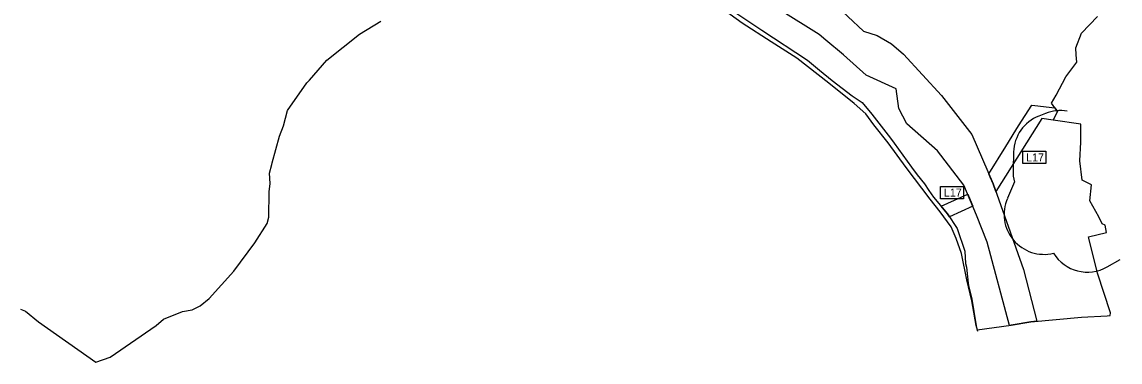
# Model space of a CAD drawing. Extents: x -547623 to -532764, y -1096714 to -1086523.
# Drawn here: x -540221 to -538849, y -1093364 to -1092939 of the extents above; entities that cross this region are included whole.
import ezdxf

# ---------------------------------------------------------------- set-up
doc = ezdxf.new("R2010")
doc.units = 0
for name, color, linetype in [('Vrstva 22', 7, 'Continuous'), ('Vrstva 23', 7, 'Continuous'), ('Vrstva 33', 7, 'Continuous'), ('Vrstva 36', 7, 'Continuous'), ('Vrstva 7', 7, 'Continuous')]:
    doc.layers.add(name, color=color, linetype=linetype)

msp = doc.modelspace()

# ---------------------------------------------------------------- linework, layer by layer
at = {"layer": 'Vrstva 22'}
for points in [[(-539330.4, -1092926.8), (-539296.6, -1092949.6), (-539239.8, -1092987), (-539224.6, -1092999.6), (-539209, -1093012.5), (-539183.7, -1093031.6), (-539171.3, -1093040), (-539159.3, -1093054.5), (-539136, -1093084.3), (-539131.5, -1093090.8), (-539109.7, -1093120.6), (-539102.6, -1093130.1), (-539093.6, -1093141.5), (-539088, -1093149.9), (-539082.1, -1093158), (-539064.8, -1093179.1), (-539052.7, -1093197.2), (-539043, -1093225.6), (-539042.3, -1093241), (-539041, -1093245.6), (-539039, -1093265.6), (-539038.6, -1093268.5), (-539036.7, -1093275.3), (-539034.4, -1093285.9), (-539029, -1093318.9), (-539027.6, -1093324.2), (-538985.4, -1093318.4), (-538960.5, -1093314.1), (-538897.5, -1093308.3), (-538865.1, -1093306.6), (-538861.7, -1093306.2), (-538861.3, -1093302.7), (-538877.2, -1093253.4), (-538888, -1093209.4), (-538888.4, -1093207.9), (-538866.2, -1093202.4), (-538867.9, -1093193), (-538871.4, -1093191.4), (-538875.6, -1093182.6), (-538887.1, -1093162.9), (-538884.8, -1093142.8), (-538896.7, -1093137), (-538899.3, -1093112.9), (-538898.2, -1093089.6), (-538898.1, -1093067), (-538932.8, -1093061.8), (-538927.5, -1093050.9), (-538935, -1093040.8), (-538929, -1093030.8), (-538916.9, -1093007.6), (-538903, -1092989.5), (-538903.9, -1092980.2), (-538904.6, -1092971.6), (-538897.2, -1092953.3), (-538877.3, -1092932.2)], [(-540223.3, -1093298.3), (-540217.1, -1093300.8), (-540200.6, -1093314.2), (-540129, -1093364.4), (-540110.9, -1093358.4), (-540053.5, -1093318.6), (-540044.5, -1093310.9), (-540020.8, -1093301.3), (-540008.8, -1093299.1), (-539998.5, -1093294), (-539987.2, -1093284.7), (-539956.7, -1093250.6), (-539930.5, -1093215.2), (-539915.1, -1093191.1), (-539912.8, -1093183.3), (-539912.5, -1093151.7), (-539911.3, -1093141), (-539912.2, -1093128), (-539908.9, -1093117.4), (-539908.7, -1093115.3), (-539899.6, -1093081.8), (-539894.3, -1093069), (-539889.5, -1093049.8), (-539865.5, -1093015.4), (-539862.3, -1093012.4), (-539861.9, -1093011.8), (-539840.5, -1092987), (-539799.6, -1092954.2), (-539772.9, -1092938.3)]]:
    msp.add_lwpolyline(points, dxfattribs=at)
at = {"layer": 'Vrstva 23'}
for p, q in [((-538942.5, -1093053.5), (-538950.7, -1093056.8)), ((-538982.2, -1093101.8), (-538982.9, -1093124.2)), ((-538981, -1093139.2), (-538989.9, -1093159.6)), ((-538865.1, -1093245.3), (-538849.2, -1093236.3))]:
    msp.add_line(p, q, dxfattribs=at)
for centre, start, end in [((-538932.2, -1093103.2), 111.6693, 178.2913), ((-538924, -1093100), 79.7065, 111.6693), ((-538932.9, -1093125.7), 178.2913, 195.7114), ((-538944.1, -1093179.7), 156.4077, 283.5835), ((-538889.9, -1093201.9), 211.8103, 299.6826)]:
    msp.add_arc(centre, 50, start, end, dxfattribs=at)
at = {"layer": 'Vrstva 33'}
for points in [[(-539209.1, -1092914), (-539169.7, -1092950.5), (-539152.7, -1092956), (-539134.8, -1092966.3), (-539119.6, -1092979.5), (-539072.1, -1093031.1), (-539034.4, -1093079.7), (-539007.9, -1093141.4), (-538969.8, -1093248.5), (-538953.2, -1093313.4), (-538960.5, -1093314.1), (-538985.4, -1093318.4), (-538987.2, -1093318.6), (-539015.1, -1093214.3), (-539028.4, -1093180.9), (-539044.2, -1093143.1), (-539077.3, -1093100.4), (-539115.4, -1093066.6), (-539125.6, -1093047.2), (-539129, -1093022.8), (-539166.3, -1093005.7), (-539194.7, -1092980.1), (-539216.9, -1092961.9), (-539225.1, -1092954.9), (-539273.9, -1092924.5)], [(-539011.5, -1093133), (-539013.1, -1093129.1), (-538991.9, -1093094.7), (-538979.3, -1093074.6), (-538975.9, -1093069.1), (-538959.6, -1093043.2)], [(-538959.6, -1093043.2), (-538955.5, -1093043.7)], [(-538955.5, -1093043.7), (-538930.6, -1093046.7), (-538927.5, -1093050.9), (-538932.8, -1093061.8), (-538947, -1093060)], [(-538947, -1093060), (-539004.3, -1093151.3), (-539007.9, -1093141.4), (-539011.5, -1093133)], [(-539072.7, -1093169.4), (-539039.5, -1093154.4), (-539033.2, -1093169.6), (-539062.4, -1093182.6), (-539064.8, -1093179.1), (-539072.7, -1093169.4)]]:
    msp.add_lwpolyline(points, dxfattribs=at)
at = {"layer": 'Vrstva 36'}
for points in [[(-538970.8, -1093100.7), (-538942.1, -1093100.7), (-538942.1, -1093116.2), (-538970.8, -1093116.2)], [(-539073.5, -1093144.7), (-539044.9, -1093144.7), (-539044.9, -1093160.2), (-539073.5, -1093160.2)]]:
    msp.add_lwpolyline(points, close=True, dxfattribs=at)
at = {"layer": 'Vrstva 7'}
msp.add_lwpolyline([(-539026.7, -1093326), (-539028.8, -1093318.6), (-539034.3, -1093288), (-539040.6, -1093261.6), (-539047.3, -1093228.5), (-539054, -1093209.7), (-539060.3, -1093195.2), (-539073.8, -1093176.4), (-539086.4, -1093160.8), (-539116.5, -1093121.1), (-539139.1, -1093090.2), (-539156.7, -1093067.9), (-539166.9, -1093053.8), (-539181.6, -1093040.9), (-539213, -1093015.7), (-539253.2, -1092984.3), (-539285, -1092964), (-539321.4, -1092940.7), (-539363.3, -1092909.8)], dxfattribs=at)

# ---------------------------------------------------------------- texts
at = {"layer": 'Vrstva 36'}
for p in [(-538966.5, -1093113.5), (-539069.3, -1093157.5)]:
    msp.add_text('L17', height=10, dxfattribs=at).set_placement(p)

doc.saveas('drawing.dxf')
